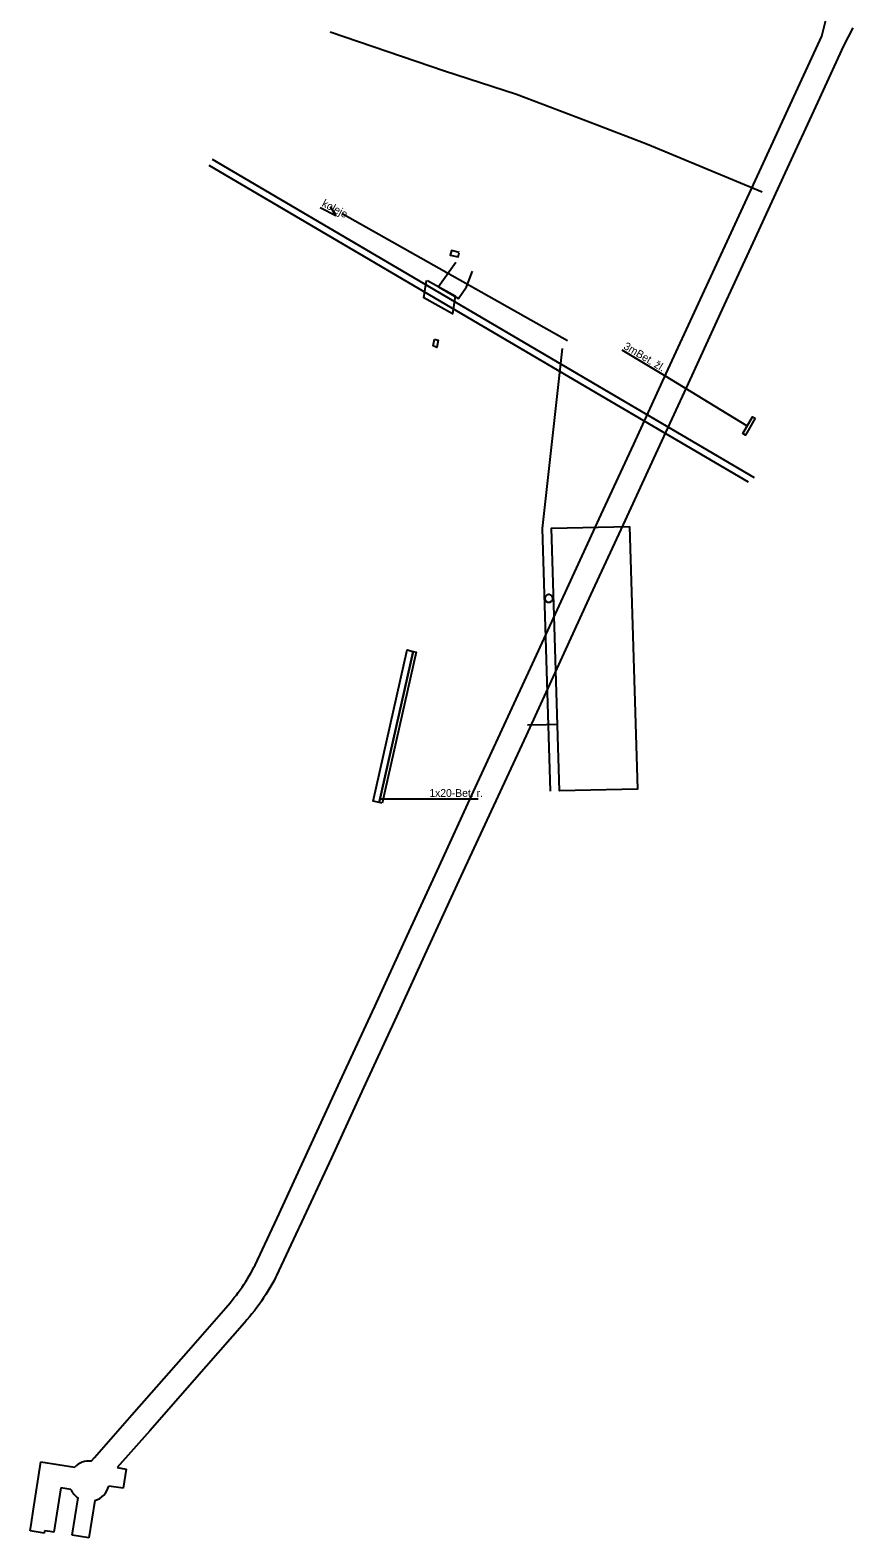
# Model space of a CAD drawing. Extents: x -739775 to -739098, y -1046233 to -1045777.
# Drawn here: x -739228.3 to -739122.1, y -1046233.5 to -1046038.8 of the extents above; entities that cross this region are included whole.
import ezdxf

# ---------------------------------------------------------------- set-up
doc = ezdxf.new("R2010")
doc.units = 0
for name, color, linetype in [('Chránička', 7, 'Continuous'), ('ST_CHRANICKA_POPIS', 7, 'Continuous'), ('ST_OBECNA_STAVBA', 7, 'Continuous'), ('ST_OBECNA_STAVBA_POPIS', 7, 'Continuous'), ('ST_TUNEL', 7, 'Continuous')]:
    doc.layers.add(name, color=color, linetype=linetype)

msp = doc.modelspace()

# ---------------------------------------------------------------- linework, layer by layer
at = {"layer": 'Chránička'}
for points in [[(-739134.732, -1046088.923), (-739135.991, -1046091.106), (-739136.337, -1046090.906), (-739135.078, -1046088.723), (-739134.732, -1046088.923)], [(-739183.293, -1046138.531), (-739184.073, -1046138.355), (-739179.683, -1046118.843), (-739178.903, -1046119.019), (-739183.293, -1046138.531)], [(-739182.899, -1046138.63), (-739183.289, -1046138.542), (-739178.904, -1046119.029), (-739178.514, -1046119.116), (-739182.899, -1046138.63)]]:
    msp.add_lwpolyline(points, close=True, dxfattribs=at)
at = {"layer": 'ST_CHRANICKA_POPIS'}
for points in [[(-739151.961, -1046080.098), (-739146.379, -1046083.465), (-739135.852, -1046089.857)], [(-739183.129, -1046138.071), (-739176.806, -1046138.054), (-739170.492, -1046138.071)]]:
    msp.add_lwpolyline(points, dxfattribs=at)
at = {"layer": 'ST_OBECNA_STAVBA'}
msp.add_line((-739188.044, -1046062.467), (-739158.976, -1046078.884), dxfattribs=at)
for points in [[(-739133.863, -1046059.71), (-739148.647, -1046053.579), (-739155.134, -1046051.079), (-739158.757, -1046049.683), (-739165.559, -1046047.119), (-739174.826, -1046044.096), (-739189.613, -1046039.092)], [(-739134.84, -1046096.622), (-739153.579, -1046085.611), (-739204.788, -1046055.52)], [(-739135.629, -1046097.163), (-739154.615, -1046086.007), (-739205.227, -1046056.267)], [(-739172.969, -1046067.528), (-739173.958, -1046067.277), (-739174.099, -1046067.858), (-739173.063, -1046068.093), (-739172.969, -1046067.559)], [(-739173.387, -1046068.834), (-739175.61, -1046071.946), (-739173.054, -1046073.445), (-739172.026, -1046071.946), (-739171.232, -1046069.918)], [(-739177.029, -1046071.123), (-739173.484, -1046073.1), (-739173.829, -1046075.424), (-739177.531, -1046073.383), (-739177.186, -1046071.123)], [(-739176.136, -1046078.697), (-739175.666, -1046078.822), (-739175.854, -1046079.795), (-739176.325, -1046079.576), (-739176.136, -1046078.728)], [(-739159.655, -1046079.901), (-739161.546, -1046096.976), (-739162.232, -1046103.17), (-739161.191, -1046137.073)], [(-739150.973, -1046102.88), (-739149.932, -1046136.821), (-739159.992, -1046137.037), (-739161.033, -1046103.134), (-739150.973, -1046102.88)], [(-739161.402, -1046111.664), (-739161.621, -1046111.748), (-739161.839, -1046111.966), (-739161.902, -1046112.278), (-739161.777, -1046112.538), (-739161.569, -1046112.684), (-739161.236, -1046112.684), (-739161.028, -1046112.538), (-739160.882, -1046112.33), (-739160.882, -1046112.07), (-739161.007, -1046111.862), (-739161.142, -1046111.748), (-739161.34, -1046111.685), (-739161.496, -1046111.685)], [(-739160.314, -1046128.476), (-739161.72, -1046128.508), (-739164.133, -1046128.564)]]:
    msp.add_lwpolyline(points, dxfattribs=at)
at = {"layer": 'ST_OBECNA_STAVBA_POPIS'}
msp.add_lwpolyline([(-739190.873, -1046061.709), (-739188.869, -1046062.764), (-739189.549, -1046061.626)], dxfattribs=at)
at = {"layer": 'ST_TUNEL'}
for p, q in [((-739126.155, -1046039.581), (-739125.484, -1046037.01)), ((-739122.148, -1046038.533), (-739123.342, -1046040.824)), ((-739129.506, -1046046.857), (-739126.155, -1046039.581)), ((-739123.342, -1046040.824), (-739126.709, -1046048.158)), ((-739133.684, -1046055.925), (-739129.506, -1046046.857)), ((-739126.709, -1046048.158), (-739130.876, -1046057.212)), ((-739137.868, -1046065.001), (-739133.684, -1046055.925)), ((-739130.876, -1046057.212), (-739135.062, -1046066.287)), ((-739142.062, -1046074.104), (-739137.868, -1046065.001)), ((-739135.062, -1046066.287), (-739139.258, -1046075.393)), ((-739146.223, -1046083.149), (-739142.062, -1046074.104)), ((-739139.258, -1046075.393), (-739143.421, -1046084.457)), ((-739150.413, -1046092.251), (-739146.223, -1046083.149)), ((-739143.421, -1046084.457), (-739147.613, -1046093.546)), ((-739154.623, -1046101.35), (-739150.413, -1046092.251)), ((-739147.613, -1046093.546), (-739151.802, -1046102.628)), ((-739158.807, -1046110.425), (-739154.623, -1046101.35)), ((-739151.802, -1046102.628), (-739156.005, -1046111.732)), ((-739162.969, -1046119.499), (-739158.807, -1046110.425)), ((-739156.005, -1046111.732), (-739160.154, -1046120.772)), ((-739167.135, -1046128.572), (-739162.969, -1046119.499)), ((-739160.154, -1046120.772), (-739164.328, -1046129.865)), ((-739171.353, -1046137.682), (-739167.135, -1046128.572)), ((-739164.328, -1046129.865), (-739168.531, -1046138.959)), ((-739175.552, -1046146.807), (-739171.353, -1046137.682)), ((-739168.531, -1046138.959), (-739172.725, -1046148.058)), ((-739179.672, -1046155.77), (-739175.552, -1046146.807)), ((-739172.725, -1046148.058), (-739176.944, -1046157.232)), ((-739183.859, -1046164.861), (-739179.672, -1046155.77)), ((-739176.944, -1046157.232), (-739181.055, -1046166.165)), ((-739188.055, -1046173.978), (-739183.859, -1046164.861)), ((-739181.055, -1046166.165), (-739185.296, -1046175.39)), ((-739192.255, -1046183.11), (-739188.055, -1046173.978)), ((-739185.296, -1046175.39), (-739189.449, -1046184.408)), ((-739196.455, -1046192.219), (-739192.255, -1046183.11)), ((-739189.449, -1046184.408), (-739193.583, -1046193.363)), ((-739199.288, -1046198.264), (-739196.456, -1046192.222)), ((-739196.456, -1046192.222), (-739196.455, -1046192.219)), ((-739193.715, -1046193.645), (-739196.516, -1046199.611)), ((-739193.583, -1046193.363), (-739193.715, -1046193.645)), ((-739200.496, -1046200.394), (-739200.271, -1046200.033)), ((-739200.271, -1046200.033), (-739200.053, -1046199.669)), ((-739200.053, -1046199.669), (-739199.841, -1046199.301)), ((-739199.841, -1046199.301), (-739199.635, -1046198.929)), ((-739199.635, -1046198.929), (-739199.436, -1046198.554)), ((-739199.436, -1046198.554), (-739199.295, -1046198.276)), ((-739199.295, -1046198.276), (-739199.288, -1046198.264)), ((-739196.651, -1046199.873), (-739196.89, -1046200.323)), ((-739196.553, -1046199.682), (-739196.651, -1046199.873)), ((-739196.516, -1046199.611), (-739196.553, -1046199.682)), ((-739201.711, -1046202.135), (-739201.456, -1046201.795)), ((-739201.456, -1046201.795), (-739201.207, -1046201.451)), ((-739201.207, -1046201.451), (-739200.964, -1046201.103)), ((-739200.964, -1046201.103), (-739200.727, -1046200.751)), ((-739200.727, -1046200.751), (-739200.496, -1046200.394)), ((-739197.924, -1046202.079), (-739198.202, -1046202.507)), ((-739197.654, -1046201.647), (-739197.924, -1046202.079)), ((-739197.392, -1046201.21), (-739197.654, -1046201.647)), ((-739197.137, -1046200.769), (-739197.392, -1046201.21)), ((-739196.89, -1046200.323), (-739197.137, -1046200.769)), ((-739207.906, -1046209.3), (-739203.082, -1046203.772)), ((-739203.082, -1046203.772), (-739202.512, -1046203.127)), ((-739202.512, -1046203.127), (-739202.239, -1046202.801)), ((-739202.239, -1046202.801), (-739201.972, -1046202.47)), ((-739201.972, -1046202.47), (-739201.711, -1046202.135)), ((-739199.078, -1046203.759), (-739199.385, -1046204.166)), ((-739198.779, -1046203.347), (-739199.078, -1046203.759)), ((-739198.486, -1046202.929), (-739198.779, -1046203.347)), ((-739198.202, -1046202.507), (-739198.486, -1046202.929)), ((-739200.68, -1046205.738), (-739205.598, -1046211.353)), ((-739200.346, -1046205.355), (-739200.68, -1046205.738)), ((-739200.019, -1046204.964), (-739200.346, -1046205.355)), ((-739199.698, -1046204.568), (-739200.019, -1046204.964)), ((-739199.385, -1046204.166), (-739199.698, -1046204.568)), ((-739215.197, -1046217.596), (-739207.906, -1046209.3)), ((-739205.598, -1046211.353), (-739212.89, -1046219.649)), ((-739220.032, -1046223.096), (-739215.197, -1046217.596)), ((-739212.89, -1046219.649), (-739217.092, -1046224.416)), ((-739220.463, -1046223.575), (-739220.036, -1046223.1)), ((-739220.036, -1046223.1), (-739220.032, -1046223.096)), ((-739227.927, -1046230.044), (-739226.937, -1046223.648)), ((-739226.937, -1046223.648), (-739222.559, -1046224.345)), ((-739217.092, -1046224.416), (-739215.925, -1046224.596)), ((-739215.925, -1046224.596), (-739216.321, -1046227.084)), ((-739224.372, -1046227.043), (-739225.258, -1046232.762)), ((-739223.066, -1046227.251), (-739224.372, -1046227.043)), ((-739216.321, -1046227.084), (-739218.175, -1046226.789)), ((-739222.905, -1046233.136), (-739222.141, -1046228.333)), ((-739219.965, -1046228.661), (-739220.732, -1046233.483)), ((-739228.154, -1046231.511), (-739227.927, -1046230.044)), ((-739228.321, -1046232.586), (-739228.154, -1046231.511)), ((-739226.51, -1046232.88), (-739228.321, -1046232.586)), ((-739226.46, -1046232.57), (-739226.51, -1046232.88)), ((-739225.799, -1046232.675), (-739226.46, -1046232.57)), ((-739225.258, -1046232.762), (-739225.799, -1046232.675)), ((-739220.732, -1046233.483), (-739222.905, -1046233.136))]:
    msp.add_line(p, q, dxfattribs=at)
for start, end in [(84.73875, 135.56588), (204.64717, 236.40921), (286.43753, 346.15301)]:
    msp.add_arc((-739220.702, -1046226.166), 2.602, start, end, dxfattribs=at)

# ---------------------------------------------------------------- texts
at = {"layer": 'ST_CHRANICKA_POPIS'}
for s, rotation, p in [('3mBet. žl.', 328.89606, (-739151.832, -1046079.883)), ('1x20-Bet. r.', 359.84131, (-739176.805, -1046137.804))]:
    msp.add_text(s, height=1, rotation=rotation, dxfattribs=at).set_placement(p)
at = {"layer": 'ST_OBECNA_STAVBA_POPIS'}
msp.add_text('koleje', height=1, rotation=332.22601, dxfattribs=at).set_placement((-739190.756, -1046061.487))

doc.saveas('drawing.dxf')
